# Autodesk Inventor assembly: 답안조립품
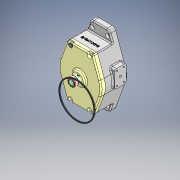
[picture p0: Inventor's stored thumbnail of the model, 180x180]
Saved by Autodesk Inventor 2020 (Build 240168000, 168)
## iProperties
Created: 2023-11
Part Number: 답안조립품
Document SubType Name: Weldment
Designer: CAD14
Weld Material: Welded Aluminum-6061
Author: CAD14
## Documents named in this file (14)
- C:\Users\CAD14\Desktop\731106V1010\답안조립품.iam
- C:\Users\CAD14\Desktop\731106V1010\본체.ipt
- C:\Users\CAD14\Desktop\731106V1010\축.ipt
- C:\Users\CAD14\Desktop\731106V1010\오일레스 부시.ipt
- C:\Users\CAD14\Desktop\731106V1010\오일 실 14 25 4.ipt
- C:\Users\CAD14\Desktop\731106V1010\평행 키 5x5x22.ipt
- C:\Users\CAD14\Desktop\731106V1010\육각 소켓 머리 볼트 M6 x 12.ipt
- C:\Users\CAD14\Desktop\731106V1010\DU 부시.ipt
- C:\Users\CAD14\Desktop\731106V1010\내접기어.ipt
- C:\Users\CAD14\Desktop\731106V1010\크레센트.ipt
- C:\Users\CAD14\Desktop\731106V1010\스퍼기어.ipt
- C:\Users\CAD14\Desktop\731106V1010\육각 소켓 머리 볼트 M4 x 30.ipt
- C:\Users\CAD14\Desktop\731106V1010\커버.ipt
- C:\Users\CAD14\Desktop\731106V1010\O링 G90.ipt
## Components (2 placed, 2 different names)
1. DU 부시:1
2. O링 G90:1
